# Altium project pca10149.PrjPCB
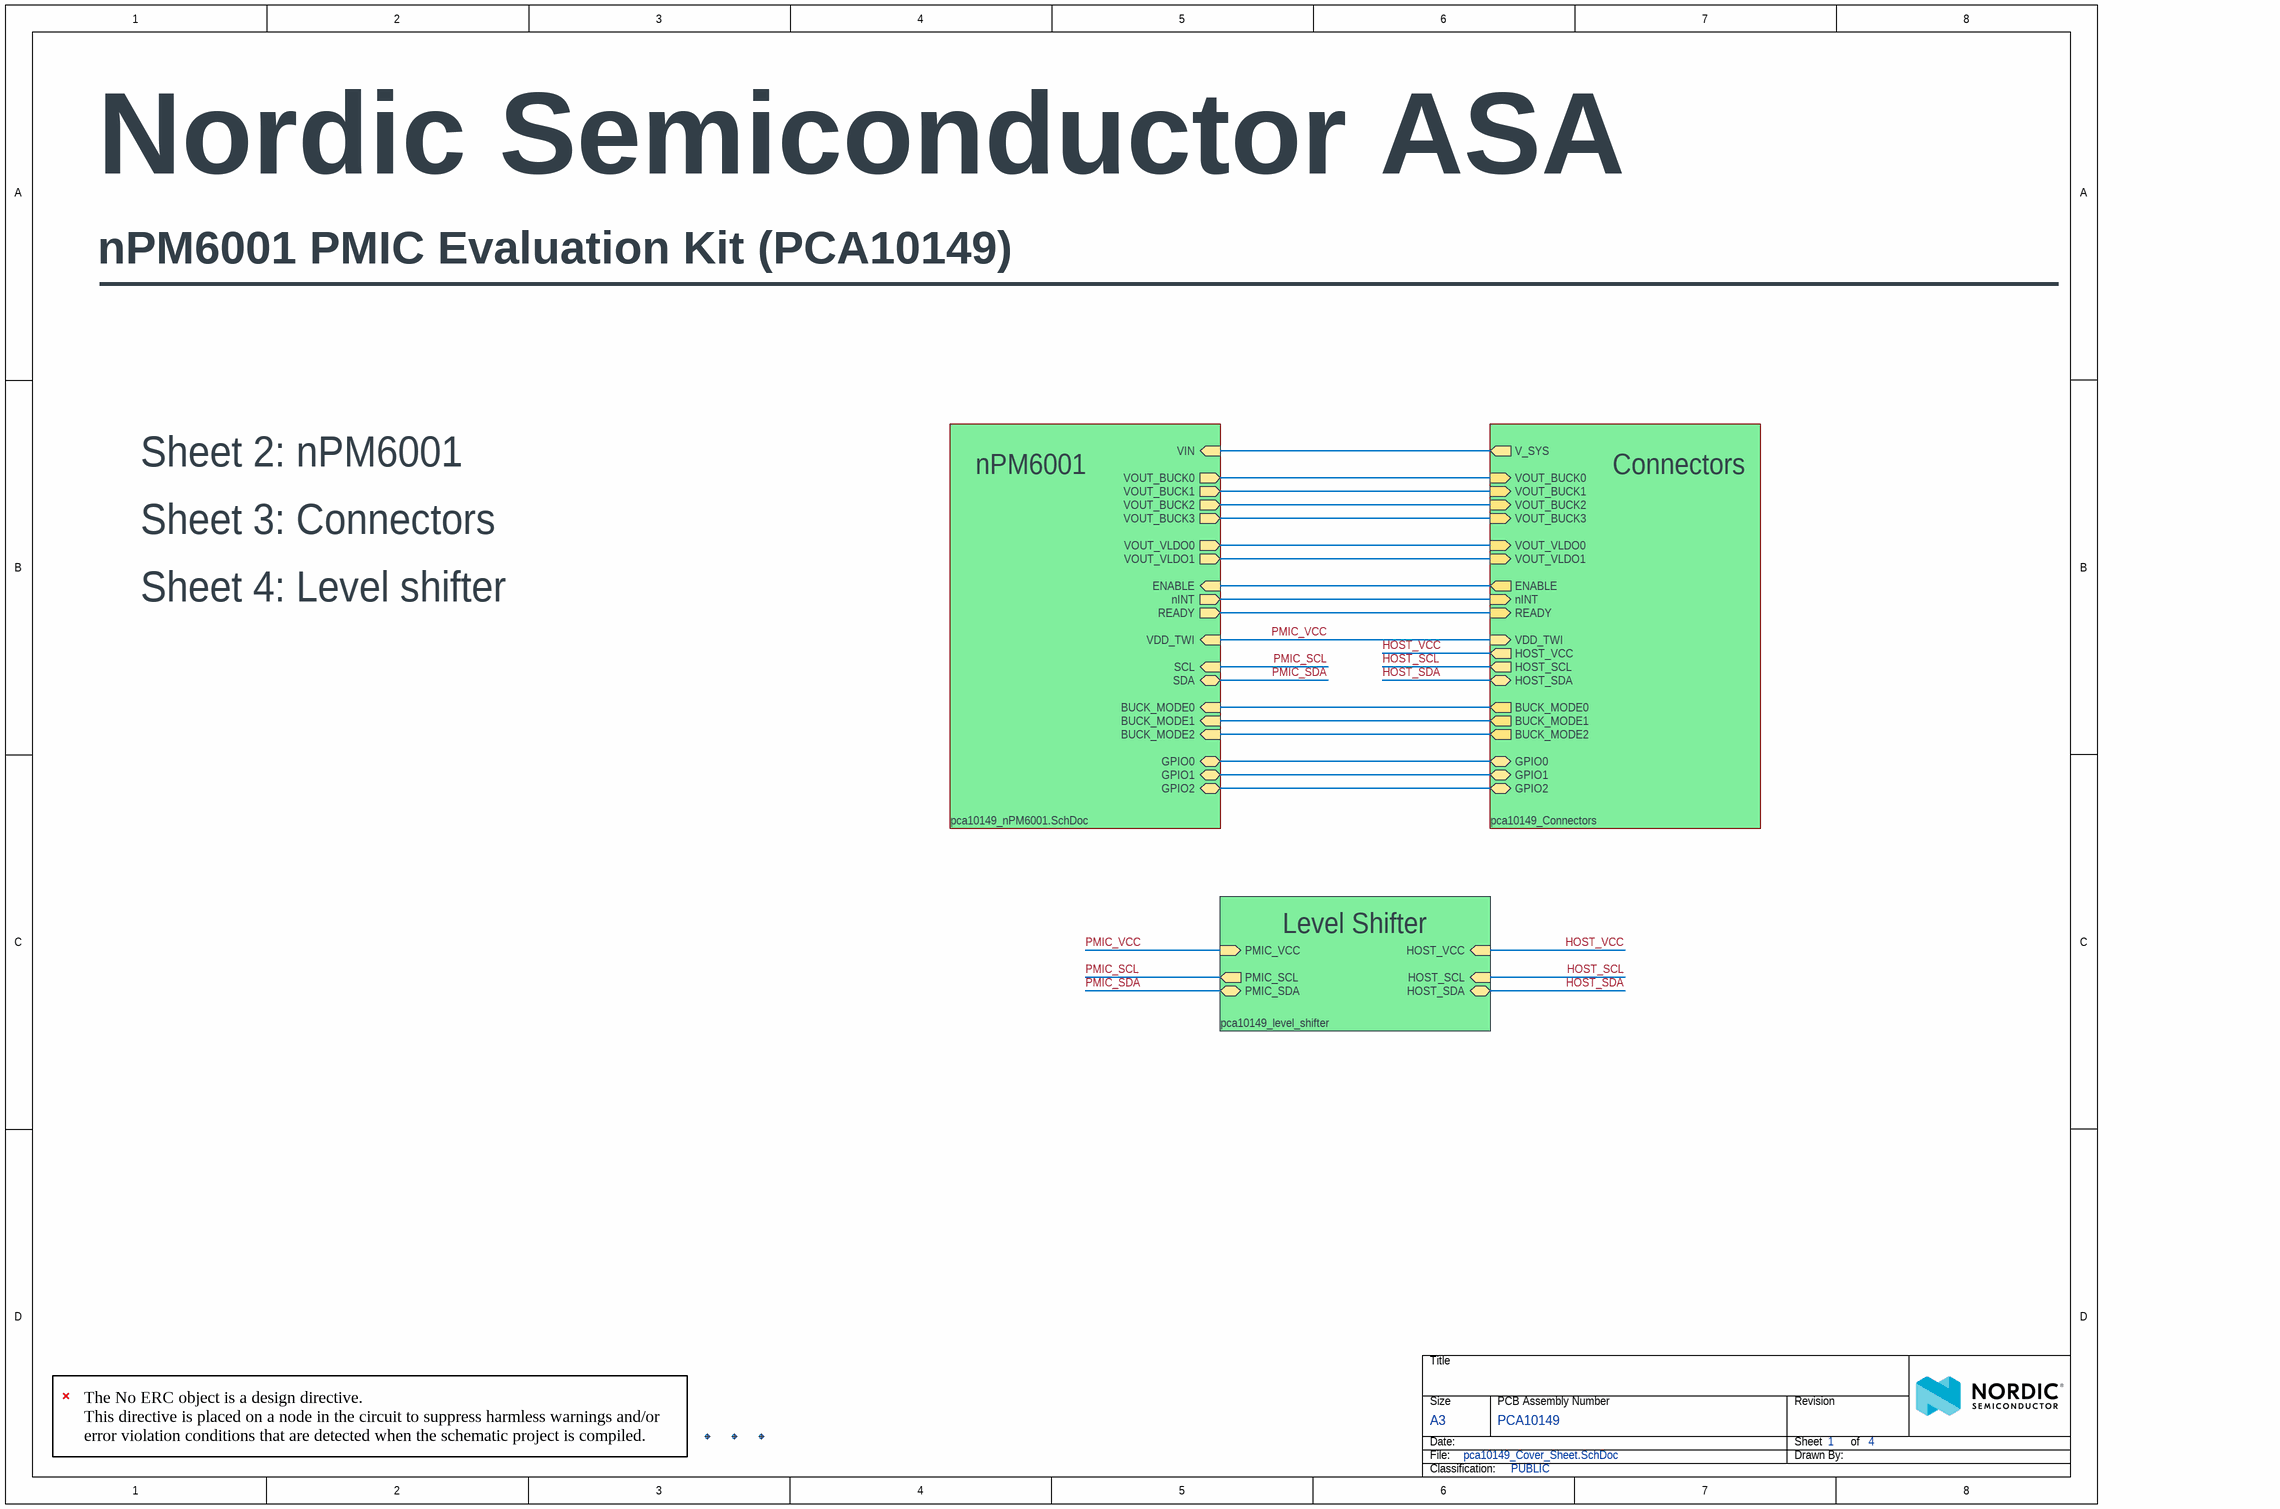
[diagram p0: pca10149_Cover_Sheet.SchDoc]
SurfaceFinish: ENIG Gold; SoldermaskColor: Blue; SilkscreenColor: White; ProductName: nPM6001 Evaluation kit PCB; PCBStackup: 6001; PCBRevision: 0003KOD1; PCBNumber: 400663; PCARevision: 0.7.0; PCAName: PCA10149; Organization: Nordic Semiconductor; NrOfLayers: 6; Dielectric: FR-4; Designer: KOD1; Compliance: RoHS, REACH, Halogen-Free; Classification: PUBLIC; BoardTitle: nPM6001 Evaluation kit; BoardThickness: 1.6mm
4 sheets, 78 parts. Net scope: hierarchical (ports join the sheet entries above them; power ports are global).
Board file: 400663.PcbDoc
Sheets:
  pca10149_Cover_Sheet.SchDoc
    nPM6001 = pca10149_nPM6001.SchDoc
    Connectors = pca10149_Connectors.SchDoc
    Level Shifter = pca10149_level_shifter.SchDoc

## Sheet pca10149_Cover_Sheet.SchDoc: =BoardTitle
size A3; Organization: Nordic Semiconductor; DocumentNumber: 1; Revision: 0.7.0; SheetNumber: 1; SheetTotal: 4; Author: KOD1; CompanyName: Nordic Semiconductor; DrawnBy: KOD1; DocumentSize: A3

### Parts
Fid1  Fiducial mark  [Fiducial]  (value not drawn)
Fid2  Fiducial mark  [Fiducial]  (value not drawn)
Fid3  Fiducial mark  [Fiducial]  (value not drawn)

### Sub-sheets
Connectors = pca10149_Connectors: ENABLE (out), BUCK_MODE0 (out), BUCK_MODE1 (out), BUCK_MODE2 (out), VOUT_BUCK1 (in), VOUT_BUCK3 (in), VOUT_VLDO0 (in), VOUT_VLDO1 (in), nINT (in), READY (in), VOUT_BUCK2 (in), VOUT_BUCK0 (in), HOST_SDA (bidir), HOST_SCL (out), HOST_VCC (out), VDD_TWI (in), GPIO0 (bidir), GPIO1 (bidir), GPIO2 (bidir), V_SYS (out)
Level Shifter = pca10149_level_shifter: HOST_SDA (bidir), HOST_SCL (in), HOST_VCC (in), PMIC_SDA (bidir), PMIC_SCL (out), PMIC_VCC (in)
nPM6001 = pca10149_nPM6001.SchDoc: ENABLE (in), READY (out), VOUT_VLDO0 (out), VOUT_VLDO1 (out), GPIO1 (bidir), VDD_TWI (in), BUCK_MODE1 (in), GPIO0 (bidir), SCL (in), VOUT_BUCK3 (out), SDA (bidir), BUCK_MODE2 (in), VOUT_BUCK2 (out), BUCK_MODE0 (in), nINT (out), VOUT_BUCK1 (out), VOUT_BUCK0 (out), GPIO2 (bidir), VIN (in)

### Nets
BUCK_MODE0: sheet nPM6001/BUCK_MODE0, sheet Connectors/BUCK_MODE0
BUCK_MODE1: sheet nPM6001/BUCK_MODE1, sheet Connectors/BUCK_MODE1
BUCK_MODE2: sheet nPM6001/BUCK_MODE2, sheet Connectors/BUCK_MODE2
ENABLE: sheet nPM6001/ENABLE, sheet Connectors/ENABLE
GPIO0: sheet nPM6001/GPIO0, sheet Connectors/GPIO0
GPIO1: sheet nPM6001/GPIO1, sheet Connectors/GPIO1
GPIO2: sheet nPM6001/GPIO2, sheet Connectors/GPIO2
HOST_SCL: sheet Connectors/HOST_SCL, sheet Level Shifter/HOST_SCL
HOST_SDA: sheet Connectors/HOST_SDA, sheet Level Shifter/HOST_SDA
HOST_VCC: sheet Connectors/HOST_VCC, sheet Level Shifter/HOST_VCC
nINT: sheet nPM6001/nINT, sheet Connectors/nINT
PMIC_SCL: sheet nPM6001/SCL, sheet Level Shifter/PMIC_SCL
PMIC_SDA: sheet nPM6001/SDA, sheet Level Shifter/PMIC_SDA
PMIC_VCC: sheet nPM6001/VDD_TWI, sheet Connectors/VDD_TWI, sheet Level Shifter/PMIC_VCC
READY: sheet nPM6001/READY, sheet Connectors/READY
VIN: sheet nPM6001/VIN, sheet Connectors/V_SYS
VOUT_BUCK0: sheet nPM6001/VOUT_BUCK0, sheet Connectors/VOUT_BUCK0
VOUT_BUCK1: sheet nPM6001/VOUT_BUCK1, sheet Connectors/VOUT_BUCK1
VOUT_BUCK2: sheet nPM6001/VOUT_BUCK2, sheet Connectors/VOUT_BUCK2
VOUT_BUCK3: sheet nPM6001/VOUT_BUCK3, sheet Connectors/VOUT_BUCK3
VOUT_VLDO0: sheet nPM6001/VOUT_VLDO0, sheet Connectors/VOUT_VLDO0
VOUT_VLDO1: sheet nPM6001/VOUT_VLDO1, sheet Connectors/VOUT_VLDO1

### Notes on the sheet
- Nordic Semiconductor ASA
- nPM6001 PMIC Evaluation Kit (PCA10149)
- ________________________________________________________________
- Sheet 2: nPM6001
- Sheet 3: Connectors
- Sheet 4: Level shifter
- (near Fid1) The No ERC object is a design directive.
  This directive is placed on a node in the circuit to suppress harmless warnings and/or error violation conditions that are detected when the schematic project is compiled.

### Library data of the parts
Fid1-Fid3 = Fid-Mark: Manufacturer: N.A.; Part number NEMS: 100500073; Value: N.A.; Pad Count: 1; Component Status: Active

## Sheet pca10149_nPM6001.SchDoc: =BoardTitle
size A3; Organization: Nordic Semiconductor; DocumentNumber: 2; Revision: 0.7.0; SheetNumber: 2; SheetTotal: 4; Author: KOD1; CompanyName: Nordic Semiconductor; DrawnBy: KOD1; DocumentSize: A3
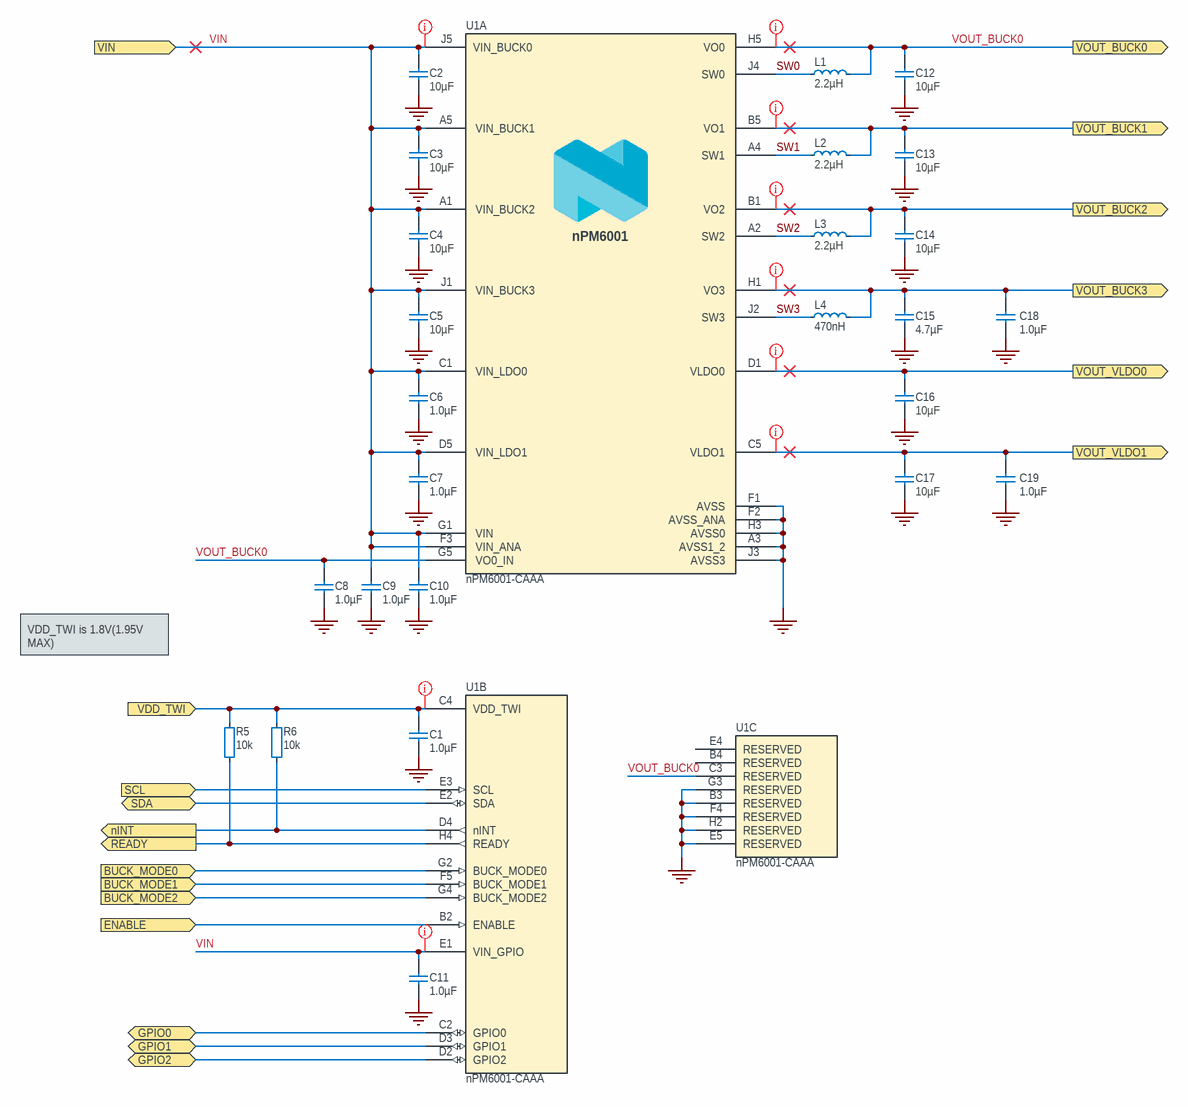
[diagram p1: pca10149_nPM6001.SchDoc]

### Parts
C1  1.0µF  [CAPC0603X03L_C]
C2  10µF  [CAPC1608X06L]
C3  10µF  [CAPC1608X06L]
C4  10µF  [CAPC1608X06L]
C5  10µF  [CAPC1608X06L]
C6  1.0µF  [CAPC0603X03L_C]
C7  1.0µF  [CAPC0603X03L_C]
C8  1.0µF  [CAPC0603X03L_C]
C9  1.0µF  [CAPC0603X03L_C]
C10  1.0µF  [CAPC0603X03L_C]
C11  1.0µF  [CAPC0603X03L_C]
C12  10µF  [CAPC1608X06L]
C13  10µF  [CAPC1608X06L]
C14  10µF  [CAPC1608X06L]
C15  4.7µF  [CAPC1608X06L]
C16  10µF  [CAPC1608X06L]
C17  10µF  [CAPC1608X06L]
C18  1.0µF  [CAPC0603X03L_C]
C19  1.0µF  [CAPC0603X03L_C]
L1  2.2µH  [INDC2016X10N]
L2  2.2µH  [INDC2016X10N]
L3  2.2µH  [INDC2016X10N]
L4  470nH  [INDC1608X06L]
R5  10k  [RESC0603X03L_C]
R6  10k  [RESC0603X03L_C]
U1  nPM6001-CAAA  [BGA45C40P5X9_217X364X49]  (parts A,B,C of 3)

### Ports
BUCK_MODE0 (in), BUCK_MODE1 (in), BUCK_MODE2 (in), ENABLE (in), GPIO0 (bidir), GPIO1 (bidir), GPIO2 (bidir), nINT (out), READY (out), SCL (in), SDA (bidir), VDD_TWI (in), VIN (in), VOUT_BUCK0 (out), VOUT_BUCK1 (out), VOUT_BUCK2 (out), VOUT_BUCK3 (out), VOUT_VLDO0 (out), VOUT_VLDO1 (out)

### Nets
GND: C1.2 C2.1 C3.1 C4.1 C5.1 C6.2 C7.2 C8.2 C9.2 C10.2 C11.2 C12.1 C13.1 C14.1 C15.1 C16.1 C17.1 C18.2 C19.2 U1.A3(AVSS1_2) U1.B3(RESERVED) U1.E5(RESERVED) U1.F1(AVSS) U1.F2(AVSS_ANA) U1.F4(RESERVED) U1.G3(RESERVED) U1.H2(RESERVED) U1.H3(AVSS0) U1.J3(AVSS3)
BUCK_MODE0: U1.G2(BUCK_MODE0) ; port BUCK_MODE0
BUCK_MODE1: U1.F5(BUCK_MODE1) ; port BUCK_MODE1
BUCK_MODE2: U1.G4(BUCK_MODE2) ; port BUCK_MODE2
ENABLE: U1.B2(ENABLE) ; port ENABLE
GPIO0: U1.C2(GPIO0) ; port GPIO0
GPIO1: U1.D3(GPIO1) ; port GPIO1
GPIO2: U1.D2(GPIO2) ; port GPIO2
nINT: R6.1 U1.D4(nINT) ; port nINT
PMIC_SCL: U1.E3(SCL) ; port SCL
PMIC_SDA: U1.E2(SDA) ; port SDA
PMIC_VCC: C1.1 R5.2 R6.2 U1.C4(VDD_TWI) ; port VDD_TWI
READY: R5.1 U1.H4(READY) ; port READY
SW0: L1.1 U1.J4(SW0)
SW1: L2.1 U1.A4(SW1)
SW2: L3.1 U1.A2(SW2)
SW3: L4.1 U1.J2(SW3)
VIN: C2.2 C3.2 C4.2 C5.2 C6.1 C7.1 C9.1 C10.1 C11.1 U1.A1(VIN_BUCK2) U1.A5(VIN_BUCK1) U1.C1(VIN_LDO0) U1.D5(VIN_LDO1) U1.E1(VIN_GPIO) U1.F3(VIN_ANA) U1.G1(VIN) U1.J1(VIN_BUCK3) U1.J5(VIN_BUCK0) ; port VIN
VOUT_BUCK0: C8.1 C12.2 L1.2 U1.C3(RESERVED) U1.G5(VO0_IN) U1.H5(VO0) ; port VOUT_BUCK0
VOUT_BUCK1: C13.2 L2.2 U1.B5(VO1) ; port VOUT_BUCK1
VOUT_BUCK2: C14.2 L3.2 U1.B1(VO2) ; port VOUT_BUCK2
VOUT_BUCK3: C15.2 C18.1 L4.2 U1.H1(VO3) ; port VOUT_BUCK3
VOUT_VLDO0: C16.2 U1.D1(VLDO0) ; port VOUT_VLDO0
VOUT_VLDO1: C17.2 C19.1 U1.C5(VLDO1) ; port VOUT_VLDO1

Not connected (* = marked no-connect by the designer): U1 B4(RESERVED) E4(RESERVED)

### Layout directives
net class POWER: PMIC_VCC, VIN, VOUT_BUCK0, VOUT_BUCK1, VOUT_BUCK2, VOUT_BUCK3, VOUT_VLDO0, VOUT_VLDO1
net class POWER; rule Supply Nets [Voltage = 0.000]: VIN

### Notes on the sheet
- VDD_TWI is 1.8V(1.95V MAX)

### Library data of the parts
C1 C6-C11 = C0201-1µ0: Capacitor, X5R, ±10%; Manufacturer: N.A.; Part number IPS: 00000001723; Pad Count: 2; Note: 10V
C2-C5 C12-C14 C16 C17 = C0603-10µ-10V-X7T-GRM188D71A106MA73: Capacitor, X7T, ±20%, 10V; Manufacturer: Murata; Part number IPS: 00000004696; Pad Count: 2; Note: 10VDC; Artikkelnr Noca: N.A.
C15 = C0603-4µ7: Capacitor, X5R, ±10%, 6.3V; Manufacturer: N.A.; Part number IPS: 00000007783; Part number NEMS: 100200274; Pad Count: 2; Artikkelnr Noca: 20069060; Component Status: Active
C18 C19 = C0201-1µ0: Capacitor, X5R, ±10%; Manufacturer: N.A.; Part number IPS: 00000001723; Part number NEMS: 100200084; Pad Count: 2; Note: 10V; Component Status: Active
L1-L3 = CIGT201610EH2R2MNE: FIXED IND 2.2UH 2.5A 87MOHM SMD; Manufacturer: Samsung Electro-Mechanics; Part number Norautron: 26521789; Pad Count: 2; Note: 2.2µH Unshielded Thin Film Inductor 2.5A 87mOhm Max 0806 (2016 Metric); Artikkelnr Noca: N.A.
L4 = L0603-470n-1.9A-85mohm: FIXED IND 470NH 1.9A 85 MOHM SMD; Manufacturer: Taiyo Yuden; Manufacturer Part Number: MCFK1608TR47M; Pad Count: 2; Note: -40°C ~ 125°C; Artikkelnr Noca: N.A.
R5 R6 = R0201-10k: Resistor, ±1%, 0.05W; Manufacturer: N.A.; Part number IPS: 00000001255; Part number Norautron: 26107101; Part number NEMS: 100100065; Pad Count: 2; Note: Chip Res 1%; Component Status: Active
U1 = nPM6001-CAAA: Low-power and high efficiency PMIC; Manufacturer: Nordic Semiconductor; Part number NEMS: 102000251; Pad Count: 45; Note: N.A.; Component Status: Active

## Sheet pca10149_Connectors.SchDoc: =BoardTitle
size A3; Organization: Nordic Semiconductor; DocumentNumber: 3; Revision: 0.7.0; SheetNumber: 3; SheetTotal: 4; Author: KOD1; CompanyName: Nordic Semiconductor; DrawnBy: KOD1; DocumentSize: A3
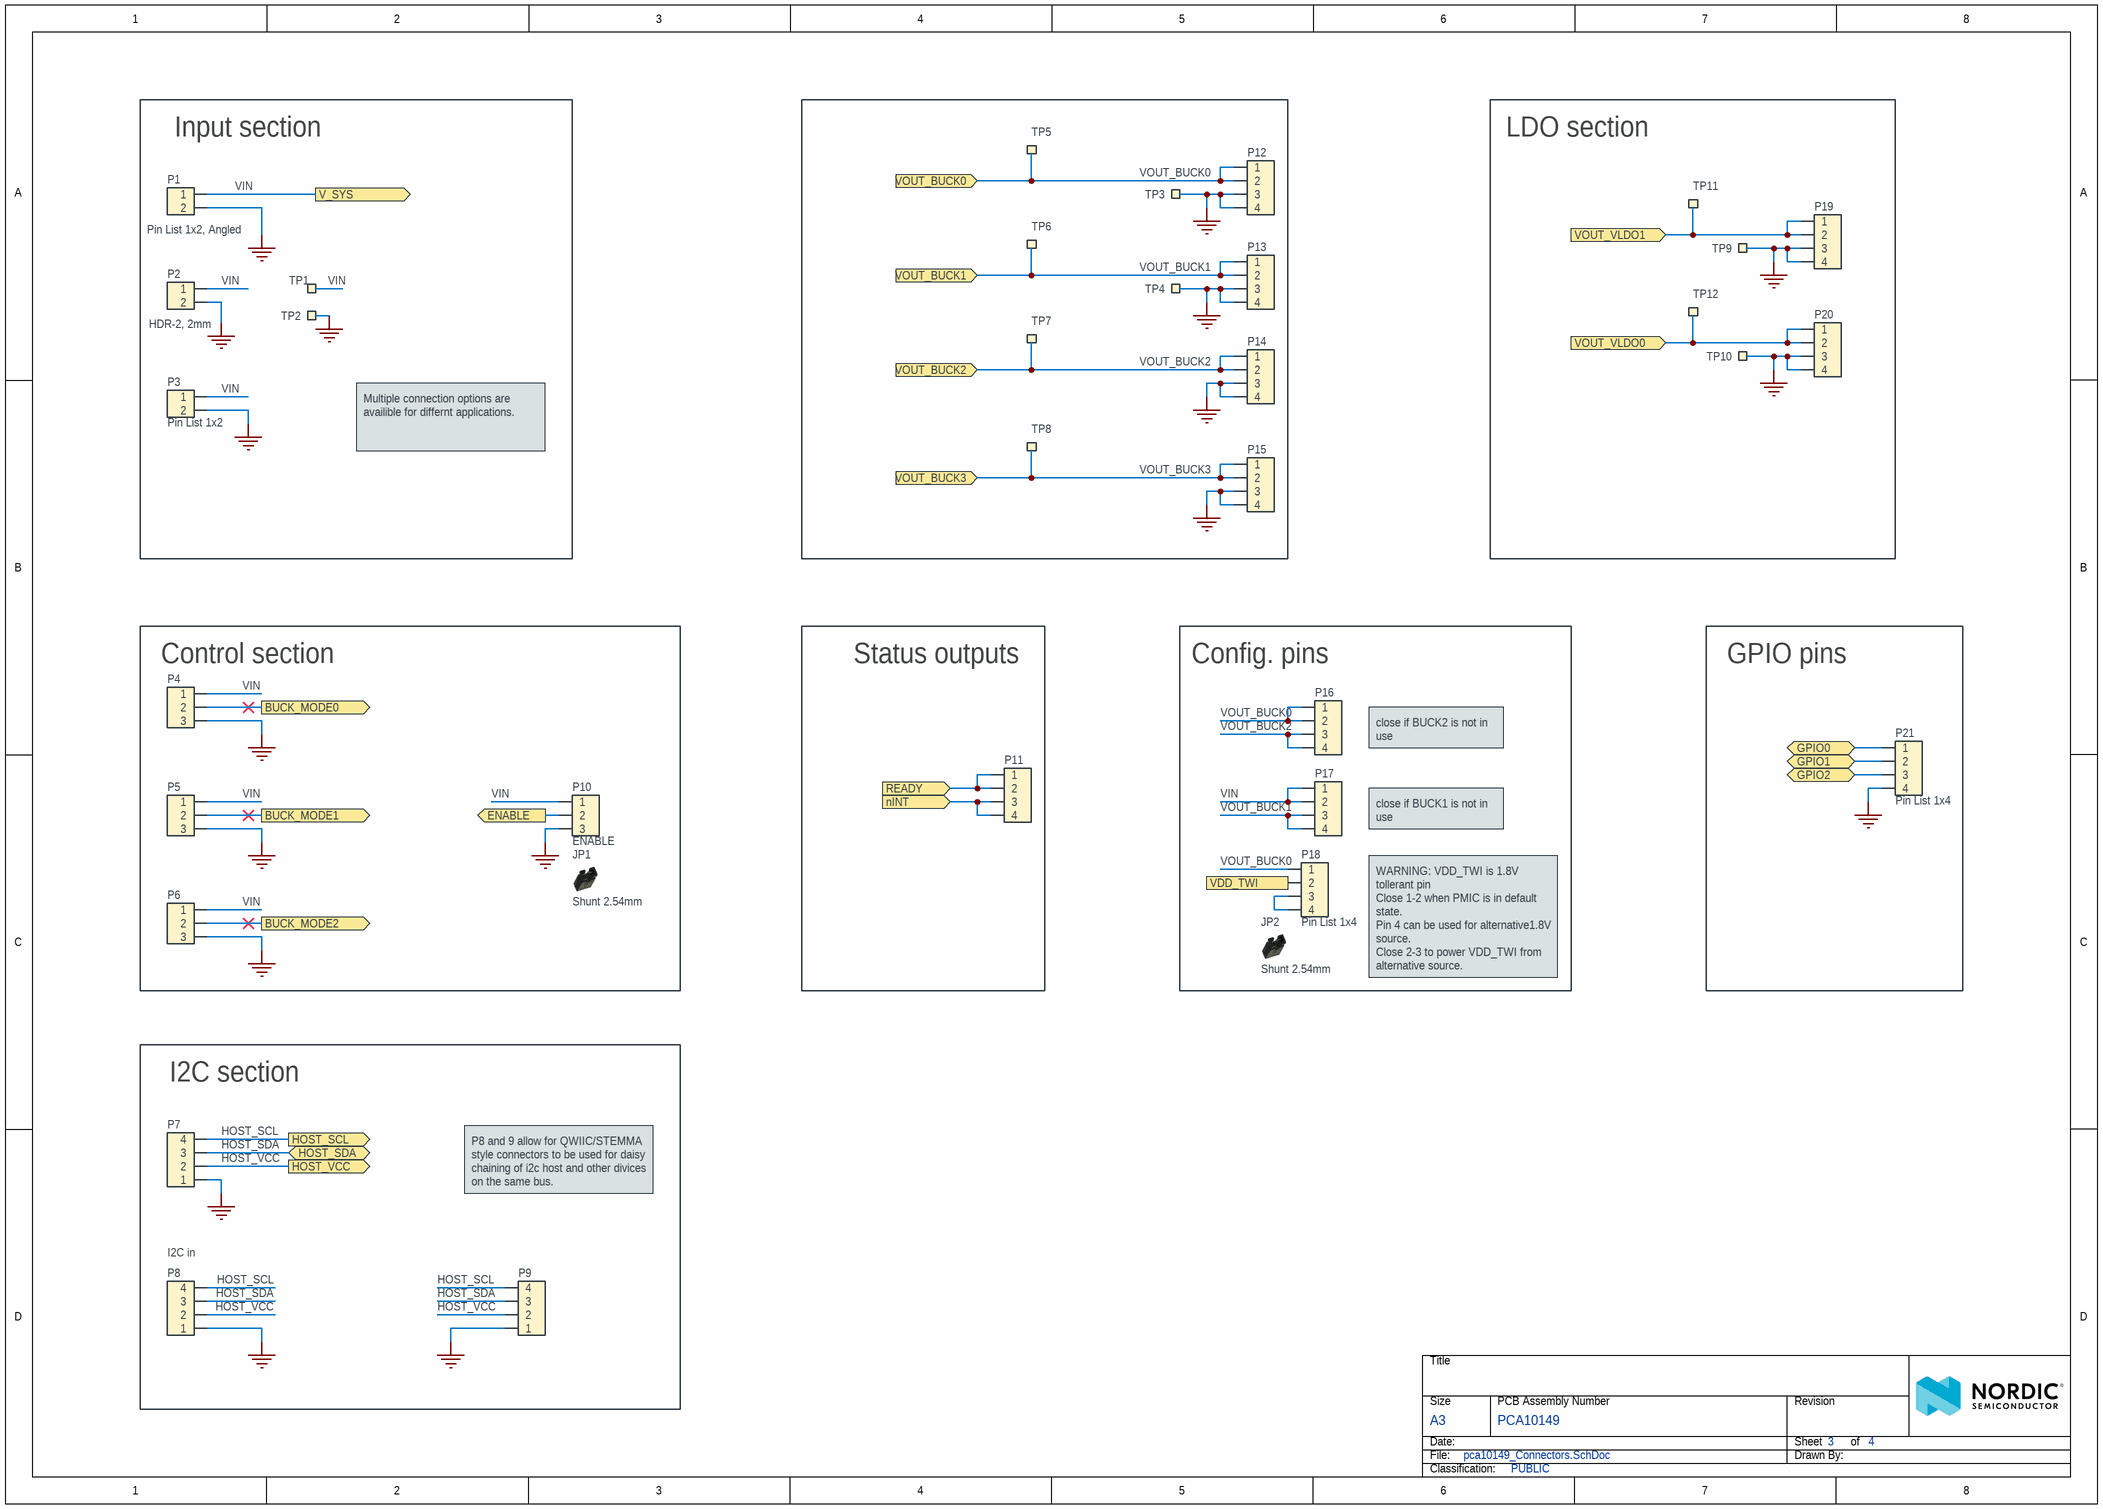
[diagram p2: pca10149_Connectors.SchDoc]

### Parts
JP1  Shunt 2.54mm  [Shunt_2.54mm_Horizontal]
JP2  Shunt 2.54mm  [Shunt_2.54mm_Horizontal]
P1  Pin List 1x2, Angled  [LIST_ANG_1x2-SMD-2.54MM]
P2  HDR-2, 2mm  [S2B-PH-SM4-TB]
P3  Pin List 1x2  [LIST_1x2-NC]
P4  BUCK_MODE0  [LIST_1x3_SMD]  (value not drawn)
P5  BUCK_MODE1  [LIST_1x3_SMD]  (value not drawn)
P6  BUCK_MODE2  [LIST_1x3_SMD]  (value not drawn)
P7  Pin List 1x4  [LIST_1x4_SMD]  (value not drawn)
P8  QWIIC  [SM04B-SRSS-TB]  (value not drawn)
P9  QWIIC  [SM04B-SRSS-TB]  (value not drawn)
P10  ENABLE  [LIST_1x3_SMD]
P11  Conn 2x2  [HDR_2x2-SMD]  (value not drawn)
P12  Conn 2x2  [HDR_2x2-SMD]  (value not drawn)
P13  Conn 2x2  [HDR_2x2-SMD]  (value not drawn)
P14  Conn 2x2  [HDR_2x2-SMD]  (value not drawn)
P15  Conn 2x2  [HDR_2x2-SMD]  (value not drawn)
P16  Conn 2x2  [HDR_2x2-SMD]  (value not drawn)
P17  Conn 2x2  [HDR_2x2-SMD]  (value not drawn)
P18  Pin List 1x4  [LIST_1x4_SMD]
P19  Conn 2x2  [HDR_2x2-SMD]  (value not drawn)
P20  Conn 2x2  [HDR_2x2-SMD]  (value not drawn)
P21  Pin List 1x4  [LIST_1x4_SMD]
TP1  VIN  [Keystone_5190TR]  (value not drawn)
TP2  GND  [Keystone_5191TR]  (value not drawn)
TP3  GND  [Keystone_5191TR]  (value not drawn)
TP4  GND  [Keystone_5191TR]  (value not drawn)
TP5  BUCK0  [Keystone_5190TR]  (value not drawn)
TP6  BUCK1  [Keystone_5190TR]  (value not drawn)
TP7  BUCK2  [Keystone_5190TR]  (value not drawn)
TP8  BUCK3  [Keystone_5190TR]  (value not drawn)
TP9  GND  [Keystone_5191TR]  (value not drawn)
TP10  GND  [Keystone_5191TR]  (value not drawn)
TP11  LDO1  [Keystone_5190TR]  (value not drawn)
TP12  LDO0  [Keystone_5190TR]  (value not drawn)

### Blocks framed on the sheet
Input section: P1-P3 TP1 TP2
LDO section: P19 P20 TP9-TP12
Control section: JP1 P4-P6 P10
Status outputs: P11
Config. pins: JP2 P16-P18
GPIO pins: P21
I2C section: P7-P9

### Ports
BUCK_MODE0 (out), BUCK_MODE1 (out), BUCK_MODE2 (out), ENABLE (out), GPIO0 (bidir), GPIO1 (bidir), GPIO2 (bidir), HOST_SCL (out), HOST_SDA (bidir), HOST_VCC (out), nINT (in), READY (in), V_SYS (out), VDD_TWI (in), VOUT_BUCK0 (in), VOUT_BUCK1 (in), VOUT_BUCK2 (in), VOUT_BUCK3 (in), VOUT_VLDO0 (in), VOUT_VLDO1 (in)

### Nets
GND: P1.2 P2.2 P3.2 P4.3 P5.3 P6.3 P7.1 P8.1 P9.1 P10.3 P12.3 P12.4 P13.3 P13.4 P14.3 P14.4 P15.3 P15.4 P19.3 P19.4 P20.3 P20.4 P21.4 TP2.1 TP3.1 TP4.1 TP9.1 TP10.1
BUCK_MODE0: P4.2 ; port BUCK_MODE0
BUCK_MODE1: P5.2 ; port BUCK_MODE1
BUCK_MODE2: P6.2 ; port BUCK_MODE2
ENABLE: P10.2 ; port ENABLE
GPIO0: P21.1 ; port GPIO0
GPIO1: P21.2 ; port GPIO1
GPIO2: P21.3 ; port GPIO2
HOST_SCL: P7.4 P8.4 P9.4 ; port HOST_SCL
HOST_SDA: P7.3 P8.3 P9.3 ; port HOST_SDA
HOST_VCC: P7.2 P8.2 P9.2 ; port HOST_VCC
nINT: P11.3 P11.4 ; port nINT
PMIC_VCC: P18.2 ; port VDD_TWI
READY: P11.1 P11.2 ; port READY
VIN: P1.1 P2.1 P3.1 P4.1 P5.1 P6.1 P10.1 P17.1 P17.2 TP1.1 ; port V_SYS
VOUT_BUCK0: P12.1 P12.2 P16.1 P16.2 P18.1 TP5.1 ; port VOUT_BUCK0
VOUT_BUCK1: P13.1 P13.2 P17.3 P17.4 TP6.1 ; port VOUT_BUCK1
VOUT_BUCK2: P14.1 P14.2 P16.3 P16.4 TP7.1 ; port VOUT_BUCK2
VOUT_BUCK3: P15.1 P15.2 TP8.1 ; port VOUT_BUCK3
VOUT_VLDO0: P20.1 P20.2 TP12.1 ; port VOUT_VLDO0
VOUT_VLDO1: P19.1 P19.2 TP11.1 ; port VOUT_VLDO1
NetP18_3: P18.3 P18.4

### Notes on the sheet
- Multiple connection options are availible for differnt applications.
- close if BUCK2 is not in use
- close if BUCK1 is not in use
- WARNING: VDD_TWI is 1.8V tollerant pin
  Close 1-2 when PMIC is in default state.
  Pin 4 can be used for alternative1.8V source.
  Close 2-3 to power VDD_TWI from alternative source.
- P8 and 9 allow for QWIIC/STEMMA style connectors to be used for daisy chaining of i2c host and other divices on the same bus.
- (near P8) I2C in

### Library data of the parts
JP1 JP2 = SHUNT JUMPER 2.54mm BLACK GOLD Horizontal (Obsolete): Shunt Jumper 2.54mm Black; Manufacturer: 3M; Manufacturer Part Number: 969102-0000-DA; Part number IPS: 00000001916; Part number Norautron: N.A.; Part number NEMS: 100500644; Pad Count: 2; Note: SHUNT JUMPER .1" BLACK GOLD, h=6.00mm, w=5.00mm; Artikkelnr Noca: 56099001
P1 = Pin List Ang 1x2 SMD, 2.54mm: Pin List 1x2, 2.54mm (100mil), Right Angled, SMD; Manufacturer: W-CON; Manufacturer Part Number: 1125B-1102S0Z135R2; Part number IPS: 00000009972; Part number NEMS: 100500354; Pad Count: 2; Note: N.A.; Artikkelnr Noca: 55010023; Component Status: Active
P2 = S2B-PH-SM4-TB: 2.0mm pitch connector side entry SMD; Manufacturer: JST Sales America Inc.; Manufacturer Part Number: S2B-PH-SM4-TB(LF)(SN); Part number NEMS: 100500381; Pad Count: 2; Note: JST, Header; Artikkelnr Noca: N.A.; Component Status: Active
P3 = Pin List 1x2, N.C.: Pin List 1x2, 2.54mm (100mil); Manufacturer: N.A.; Part number NEMS: 100500298; Component Status: Active; Pad Count: 2; Assembly: Not mounted
P4-P6 P10 = Pin List 1x3 SMD: Pin List 1x3, 2.54mm (100mil), SMD; Manufacturer: W-CON; Manufacturer Part Number: 1125-1103S0M116CR02; Part number Norautron: 26470016; Part number NEMS: 100500306; Pad Count: 3; Note: N.A.; Component Status: Active
P7 P18 P21 = Pin List 1x4 SMD: Pin List 1x4, 2.54mm (100mil), SMD; Manufacturer: N.A.; Part number NEMS: 100500311; Pad Count: 4; Artikkelnr Noca: 55019234; Component Status: Active
P8 P9 = SM04B-SRSS-TB: JST SR/SH 1.0mm 4-pin; Manufacturer: JST Sales America Inc.; Part number NEMS: 100500540; Pad Count: 4; Note: N.A.; Component Status: Active
P11-P17 P19 P20 = HDR_2x2_SMD_GOLD: CONN HEADER 4POS .100" VERT 15AU; Manufacturer: Molex; Part number NEMS: 100500132; Component Status: Active; Pad Count: 4; Note: SMD, gold plating; Artikkelnr Noca: N.A.
TP1 TP5-TP8 TP11 TP12 = TP - Keystone 5190T: Miniature SMT Test Point -Red P/N 5190TR; Manufacturer Part Number: 5190T; Part number NEMS: 100500747; Component Status: Active; Pad Count: 1; Value: TP; Note: Keystone 5190TR, RED; Artikkelnr Noca: N.A.
TP2-TP4 TP9 TP10 = TP - Keystone 5191T: Miniature SMT Test Point -Red P/N 5191TR; Manufacturer Part Number: 5191T; Part number NEMS: 100500748; Component Status: Active; Pad Count: 1; Value: TP; Note: Keystone 5191TR, BLACK; Artikkelnr Noca: N.A.

## Sheet pca10149_level_shifter.SchDoc: =BoardTitle
size A4; Organization: Nordic Semiconductor; DocumentNumber: 4; Revision: 0.7.0; SheetNumber: 4; SheetTotal: 4; Author: KOD1; CompanyName: Nordic Semiconductor; DrawnBy: KOD1; DocumentSize: A4
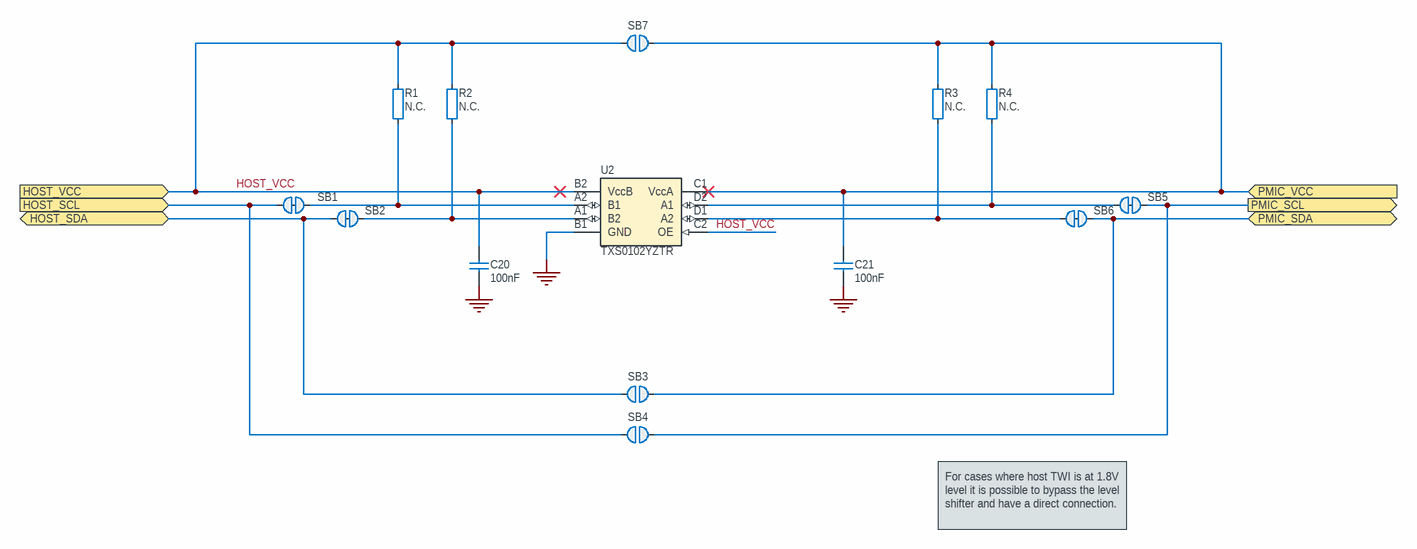
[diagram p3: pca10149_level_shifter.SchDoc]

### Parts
C20  100nF  [CAPC0603X03L_C]
C21  100nF  [CAPC0603X03L_C]
R1  N.C.  [RESC1608X06L_NC]
R2  N.C.  [RESC1608X06L_NC]
R3  N.C.  [RESC1608X06L_NC]
R4  N.C.  [RESC1608X06L_NC]
SB1  Solderbridge  [Solderbridge_SHORTED_0.4]  (value not drawn)  (net tie, no BOM)
SB2  Solderbridge  [Solderbridge_SHORTED_0.4]  (value not drawn)  (net tie, no BOM)
SB3  Solderbridge  [Solderbridge]  (value not drawn)  (no BOM)
SB4  Solderbridge  [Solderbridge]  (value not drawn)  (no BOM)
SB5  Solderbridge  [Solderbridge_SHORTED_0.4]  (value not drawn)  (net tie, no BOM)
SB6  Solderbridge  [Solderbridge_SHORTED_0.4]  (value not drawn)  (net tie, no BOM)
SB7  Solderbridge  [Solderbridge]  (value not drawn)  (no BOM)
U2  TXS0102YZTR  [BGA8C50P2X4_89X189X50]

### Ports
HOST_SCL (in), HOST_SDA (bidir), HOST_VCC (in), PMIC_SCL (out), PMIC_SDA (bidir), PMIC_VCC (in)

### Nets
GND: C20.1 C21.1 U2.B1(GND)
HOST_SCL: SB1.2 SB4.2 ; port HOST_SCL
HOST_SDA: SB2.2 SB3.2 ; port HOST_SDA
HOST_VCC: C20.2 R1.2 R2.2 SB7.2 U2.B2(VccB) U2.C2(OE) ; port HOST_VCC
PMIC_SCL: SB4.1 SB5.1 ; port PMIC_SCL
PMIC_SDA: SB3.1 SB6.1 ; port PMIC_SDA
PMIC_VCC: C21.2 R3.2 R4.2 SB7.1 U2.C1(VccA) ; port PMIC_VCC
NetR1_1: R1.1 SB1.1 U2.A2(B1)
NetR2_1: R2.1 SB2.1 U2.A1(B2)
NetR3_1: R3.1 SB6.2 U2.D1(A2)
NetR4_1: R4.1 SB5.2 U2.D2(A1)

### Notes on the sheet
- For cases where host TWI is at 1.8V level it is possible to bypass the level shifter and have a direct connection.

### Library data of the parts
C20 C21 = C0201-100n-25V-X5R: Capacitor, Ceramic, X5R, ±10%, 25V; Manufacturer: Murata; Manufacturer Part Number: GRM033R61E104KE14J; Part number NEMS: 100200459; Pad Count: 2; Artikkelnr Noca: N.A.; Component Status: Active
R1-R4 = R0603-N.C.: Not mounted; Manufacturer: N.A.; Part number NEMS: 100100373; Pad Count: 2; Note: Chip Res; Assembly: Not mounted; Component Status: Active
SB1 SB2 SB5 SB6 = Solderbridge Shorted 0.4mm: Shorted Solderbridge; Manufacturer: N.A.; Part number NEMS: 100500561; Pad Count: 2; Component Status: Active
SB3 SB4 SB7 = Solderbridge: Manufacturer: N.A.; Part number NEMS: 100500458; Pad Count: 2; Component Status: Active
U2 = TXS0102YZTR: Voltage Level Translator Bidirectional 1 Circuit 2 Channel 24Mbps 8-DSBGA; Manufacturer: Texas Instruments; Part number NEMS: 101900683; Pad Count: 8; Note: TEXAS INSTRUMENTS - TXS0102YZTR - IC, TRANSLATOR; Artikkelnr Noca: N.A.; Component Status: Active

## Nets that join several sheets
GND: pca10149_nPM6001 (29 pins), pca10149_Connectors (28 pins), pca10149_level_shifter (C20.1 C21.1 U2.B1)
BUCK_MODE0: pca10149_nPM6001 (U1.G2), pca10149_Connectors (P4.2)
BUCK_MODE1: pca10149_nPM6001 (U1.F5), pca10149_Connectors (P5.2)
BUCK_MODE2: pca10149_nPM6001 (U1.G4), pca10149_Connectors (P6.2)
ENABLE: pca10149_nPM6001 (U1.B2), pca10149_Connectors (P10.2)
GPIO0: pca10149_nPM6001 (U1.C2), pca10149_Connectors (P21.1)
GPIO1: pca10149_nPM6001 (U1.D3), pca10149_Connectors (P21.2)
GPIO2: pca10149_nPM6001 (U1.D2), pca10149_Connectors (P21.3)
HOST_SCL: pca10149_Connectors (P7.4 P8.4 P9.4), pca10149_level_shifter (SB1.2 SB4.2)
HOST_SDA: pca10149_Connectors (P7.3 P8.3 P9.3), pca10149_level_shifter (SB2.2 SB3.2)
HOST_VCC: pca10149_Connectors (P7.2 P8.2 P9.2), pca10149_level_shifter (6 pins)
nINT: pca10149_nPM6001 (R6.1 U1.D4), pca10149_Connectors (P11.3 P11.4)
PMIC_SCL: pca10149_nPM6001 (U1.E3), pca10149_level_shifter (SB4.1 SB5.1)
PMIC_SDA: pca10149_nPM6001 (U1.E2), pca10149_level_shifter (SB3.1 SB6.1)
PMIC_VCC: pca10149_nPM6001 (C1.1 R5.2 R6.2 U1.C4), pca10149_Connectors (P18.2), pca10149_level_shifter (5 pins)
READY: pca10149_nPM6001 (R5.1 U1.H4), pca10149_Connectors (P11.1 P11.2)
VIN: pca10149_nPM6001 (18 pins), pca10149_Connectors (10 pins)
VOUT_BUCK0: pca10149_nPM6001 (6 pins), pca10149_Connectors (6 pins)
VOUT_BUCK1: pca10149_nPM6001 (C13.2 L2.2 U1.B5), pca10149_Connectors (5 pins)
VOUT_BUCK2: pca10149_nPM6001 (C14.2 L3.2 U1.B1), pca10149_Connectors (5 pins)
VOUT_BUCK3: pca10149_nPM6001 (C15.2 C18.1 L4.2 U1.H1), pca10149_Connectors (P15.1 P15.2 TP8.1)
VOUT_VLDO0: pca10149_nPM6001 (C16.2 U1.D1), pca10149_Connectors (P20.1 P20.2 TP12.1)
VOUT_VLDO1: pca10149_nPM6001 (C17.2 C19.1 U1.C5), pca10149_Connectors (P19.1 P19.2 TP11.1)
